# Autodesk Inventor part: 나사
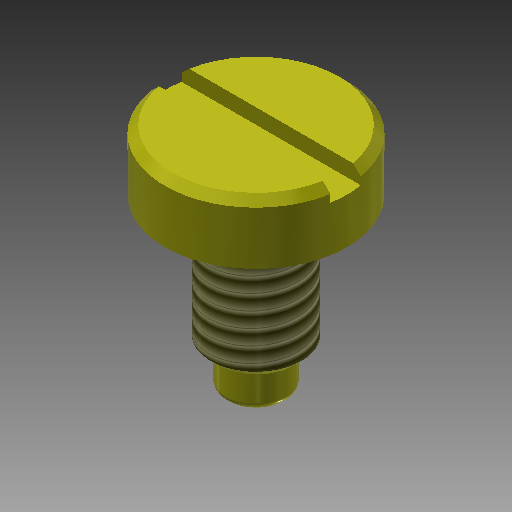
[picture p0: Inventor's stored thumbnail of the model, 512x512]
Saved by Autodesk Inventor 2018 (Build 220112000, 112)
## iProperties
Created: 2019-10
Part Number: 나사
Material: 스테인리스강
Document SubType Name: Modeling
Designer: mduedu
Density: 1 g/cm^3
Appearance: 노란색
Author: mduedu
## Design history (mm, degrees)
sketch "스케치1"
  geometry: L1 (0, 0)-(-6, 0); L2 (-6, 0)-(-6, -4); L3 (-6, -4)-(0, -4); L4 (0, -4)-(0, 0); L5 (0, -4)-(-3, -4); L6 (-3, -4)-(-3, -12.5); L7 (-3, -12.5)-(0, -12.5); L8 (0, -12.5)-(0, -4); L9 (0, -12.5)-(-2, -12.5); L10 (-2, -12.5)-(-2, -15); L11 (-2, -15)-(0, -15); L12 (0, -15)-(0, -12.5)
  constraints: 24 end point, 6 parallel, 3 horizontal, 3 perpendicular
  dimensions: "d0" = 15 distance between parallel lines of L11 L1; "d2" = 4 distance of L1.end L2.end; "d3" = 2.5 distance of L9.end L10.end; "d4" = 12 diameter of L2 L4; "d5" = 6 diameter of L6 L8; "d6" = 4 diameter of L10 L12
revolve "회전1" sketch "스케치1" stored, may be unused: angle "d7" = 90 deg
sketch "스케치2"
  geometry: L1 (2, -15)-(-2, -15) reference; L2 (-2, -15)-(-2, -12.5) reference; L3 (-2, -12.5)-(-3, -12.5) reference; L4 (-3, -12.5)-(-3, -4) reference; L5 (-3, -4)-(-6, -4) reference; L6 (-6, -4)-(-6, 0) reference; L7 (-6, 0)-(6, 0) reference; L8 (6, 0)-(6, -4) reference; L9 (6, -4)-(3, -4) reference; L10 (3, -4)-(3, -12.5) reference; L11 (3, -12.5)-(2, -12.5) reference; L12 (2, -12.5)-(2, -15) reference; L13 (0, 0)-(0, -15); L14 (-3, -4)-(-2.25, -4); L15 (-2.25, -4)-(-2.25, -4.5); L16 (-2.25, -4.5)-(-3, -4.5); L17 (-3, -4.5)-(-3, -4)
  constraints: 10 end point, 2 parallel, 1 horizontal, 1 midpoint, 1 perpendicular
  dimensions: "d8" = 4.5 diameter of L15 L13; "d10" = 0.5 distance between parallel lines of L16 L14
revolve "회전2" sketch "스케치2" stored, may be unused: angle "d11" = 90 deg
chamfer "모따기1" distance "d12" = 0.5; stored, may be unused: second distance "d13" = 2, angle "d14" = 45 deg
feature "스레드1" dims "d19" = 10, "d20" = 0
chamfer "모따기2" distance "d15" = 0.5; stored, may be unused: second distance "d16" = 2, angle "d17" = 45 deg
fillet "모깎기1" dims "d18" = 0.5
sketch "스케치3"
  geometry: L1 (-7.5, -1)-(7.5, -1); L2 (7.5, -1)-(7.5, 1); L3 (7.5, 1)-(-7.5, 1); L4 (-7.5, 1)-(-7.5, -1); L5 (-7.5, -1)-(7.5, 1); L6 (7.5, -1)-(-7.5, 1); 1 further point
  constraints: 12 end point, 2 midpoint, 2 parallel, 1 horizontal, 1 perpendicular
  dimensions: "d21" = 2 distance of L1.end L2.end; "d23" = 15 distance of L2.end L3.end
extrude "돌출1" cut sketch "스케치3" distance "d24" = 1; taper "d25" = 0 deg
node "솔리드1"
node "절단 모서리 투영1"
